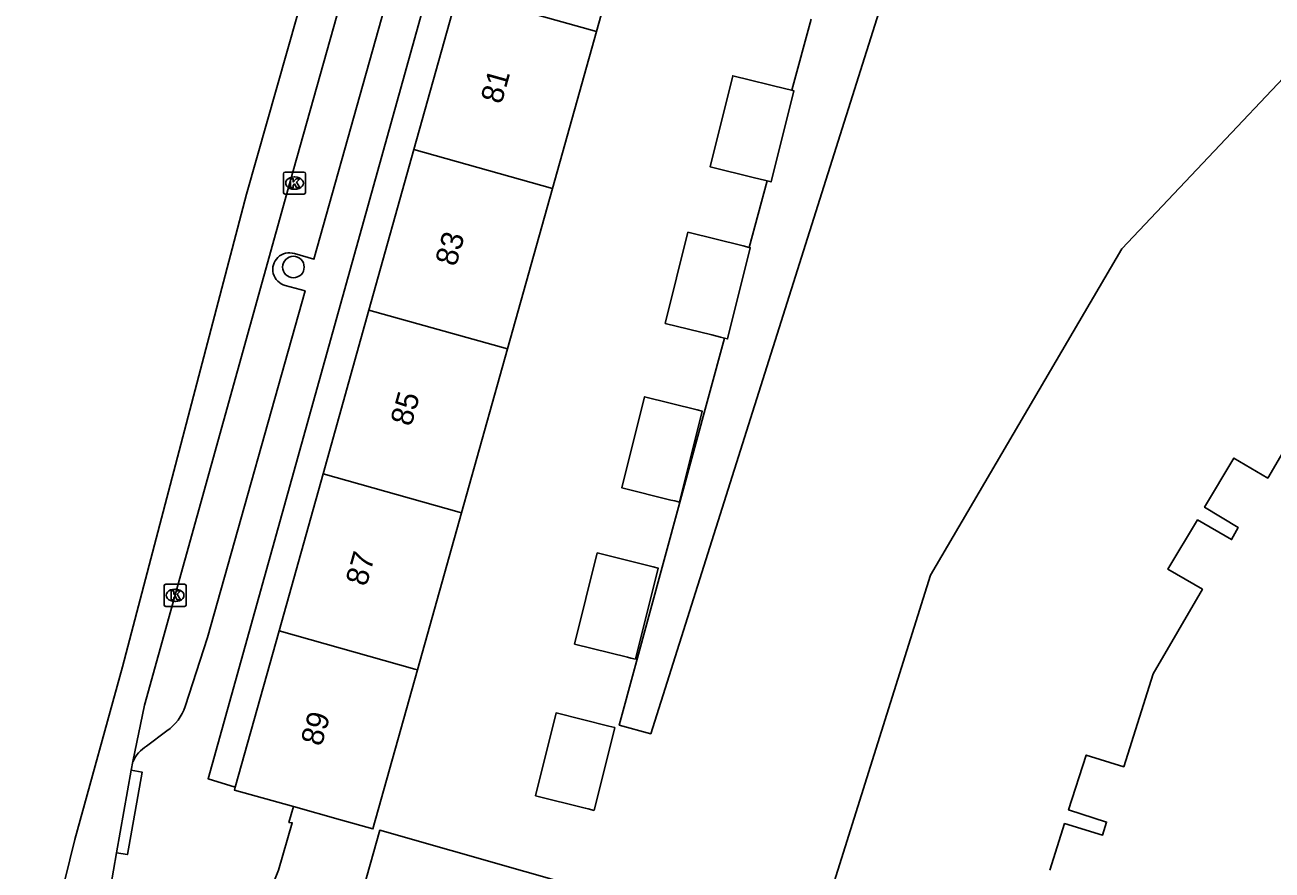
# Model space of a CAD drawing. Extents: x 163150 to 163546, y 380933 to 381635.
# Drawn here: x 163156.4 to 163213, y 381250 to 381288.4 of the extents above; entities that cross this region are included whole.
import ezdxf

# ---------------------------------------------------------------- set-up
doc = ezdxf.new("R2010")
doc.units = 0
for name, color, linetype in [('IMGEO_Boom', 7, 'Continuous'), ('IMGEO_Fietspad_gesloten', 7, 'Continuous'), ('IMGEO_Kolk', 7, 'Continuous'), ('IMGEO_Pand', 7, 'Continuous'), ('IMGEO_Pand_nummerreeks', 7, 'Continuous'), ('IMGEO_Rijbaan_lokaal_gesloten', 7, 'Continuous'), ('IMGEO_Voetpad_open', 7, 'Continuous')]:
    doc.layers.add(name, color=color, linetype=linetype)

msp = doc.modelspace()

# ---------------------------------------------------------------- linework, layer by layer
at = {"layer": 'IMGEO_Boom'}
msp.add_circle((163168.557, 381277.378), 0.489, dxfattribs=at)
at = {"layer": 'IMGEO_Fietspad_gesloten'}
for points in [[(163161.275, 381254.943), (163161.793, 381257.499), (163168.406, 381281.262), (163179.271, 381319.843), (163184.929, 381339.887), (163190.292, 381358.866), (163196.902, 381382.418), (163200.87, 381396.808), (163201.039, 381397.48), (163201.153, 381398.031), (163202.014, 381403.062), (163202.729, 381407.262)], [(163160.529, 381250.797), (163161.194, 381254.541)], [(163161.275, 381254.943), (163161.194, 381254.541)], [(163160.529, 381250.797), (163160.391, 381250), (163158.975, 381241.822), (163158.792, 381240.856)]]:
    msp.add_lwpolyline(points, dxfattribs=at)
at = {"layer": 'IMGEO_Kolk'}
for p, q in [((163168.18, 381281.688), (163169.032, 381281.688)), ((163168.105, 381280.762), (163168.105, 381281.614)), ((163168.593, 381281.468), (163168.618, 381281.468)), ((163169.106, 381281.614), (163169.106, 381280.762)), ((163169.032, 381280.688), (163168.18, 381280.688)), ((163168.616, 381280.908), (163168.591, 381280.908)), ((163162.762, 381262.978), (163163.614, 381262.978)), ((163162.687, 381262.052), (163162.687, 381262.904)), ((163163.175, 381262.758), (163163.2, 381262.758)), ((163163.688, 381262.904), (163163.688, 381262.052)), ((163163.614, 381261.978), (163162.762, 381261.978)), ((163163.198, 381262.198), (163163.173, 381262.198))]:
    msp.add_line(p, q, dxfattribs=at)
for points in [[(163168.18, 381281.688), (163169.032, 381281.688)], [(163168.105, 381280.762), (163168.105, 381281.614)], [(163168.426, 381281.388), (163168.549, 381281.388), (163168.549, 381281.237), (163168.679, 381281.388), (163168.843, 381281.388), (163168.697, 381281.237), (163168.85, 381280.988), (163168.698, 381280.988), (163168.613, 381281.152), (163168.549, 381281.085), (163168.549, 381280.988), (163168.426, 381280.988), (163168.426, 381281.388)], [(163169.106, 381281.614), (163169.106, 381280.762)], [(163169.032, 381280.688), (163168.18, 381280.688)], [(163162.762, 381262.978), (163163.614, 381262.978)], [(163162.687, 381262.052), (163162.687, 381262.904)], [(163163.008, 381262.678), (163163.131, 381262.678), (163163.131, 381262.527), (163163.261, 381262.678), (163163.425, 381262.678), (163163.279, 381262.527), (163163.432, 381262.278), (163163.28, 381262.278), (163163.195, 381262.442), (163163.131, 381262.375), (163163.131, 381262.278), (163163.008, 381262.278), (163163.008, 381262.678)], [(163163.688, 381262.904), (163163.688, 381262.052)], [(163163.614, 381261.978), (163162.762, 381261.978)]]:
    msp.add_lwpolyline(points, dxfattribs=at)
for centre, start, end in [((163168.182, 381281.612), 91.552, 178.448), ((163168.182, 381281.612), 91.552, 178.448), ((163169.03, 381281.612), 1.552, 88.448), ((163169.03, 381281.612), 1.552, 88.448), ((163168.182, 381280.764), 181.552, 268.448), ((163168.182, 381280.764), 181.552, 268.448), ((163169.03, 381280.764), 271.552, 358.448), ((163169.03, 381280.764), 271.552, 358.448), ((163162.764, 381262.902), 91.552, 178.448), ((163162.764, 381262.902), 91.552, 178.448), ((163163.612, 381262.902), 1.552, 88.448), ((163163.612, 381262.902), 1.552, 88.448), ((163162.764, 381262.054), 181.552, 268.448), ((163162.764, 381262.054), 181.552, 268.448), ((163163.612, 381262.054), 271.552, 358.448), ((163163.612, 381262.054), 271.552, 358.448)]:
    msp.add_arc(centre, 0.0765, start, end, dxfattribs=at)
for centre, major_axis, ratio, start_param, end_param in [((163168.592, 381281.188), (-0.387, 0.002), 0.722429, 4.712389, 7.853982), ((163168.617, 381281.188), (-0.39, 0.002), 0.717154, 1.570796, 4.712389), ((163163.174, 381262.478), (-0.387, 0.002), 0.722429, 4.712389, 7.853982), ((163163.199, 381262.478), (-0.39, 0.002), 0.717154, 1.570796, 4.712389)]:
    msp.add_ellipse(centre, major_axis=major_axis, ratio=ratio, start_param=start_param, end_param=end_param, dxfattribs=at)
at = {"layer": 'IMGEO_Pand'}
for points in [[(163187.968, 381233.07), (163193.271, 381250), (163197.467, 381263.396), (163206.151, 381278.206), (163217.937, 381290.687), (163232.209, 381300.168), (163248.202, 381306.183), (163251.969, 381306.664), (163251.737, 381308.49), (163248.676, 381308.083), (163248.28, 381310.782), (163251.461, 381311.208), (163254.337, 381311.635), (163256.45, 381311.907)], [(163184.36, 381295.392), (163182.308, 381288.068)], [(163176.023, 381289.839), (163174.025, 381282.711)], [(163182.308, 381288.068), (163176.023, 381289.839)], [(163182.308, 381288.068), (163180.311, 381280.941)], [(163190.057, 381281.286), (163189.94, 381281.315), (163189.487, 381281.427), (163187.471, 381281.927), (163188.499, 381286.064), (163190.967, 381285.451), (163191.174, 381285.399)], [(163190.057, 381281.286), (163190.235, 381281.242), (163191.263, 381285.377), (163191.174, 381285.399)], [(163174.025, 381282.711), (163171.985, 381275.428)], [(163174.025, 381282.711), (163180.311, 381280.941)], [(163180.311, 381280.941), (163178.271, 381273.661)], [(163188.12, 381274.155), (163187.946, 381274.198), (163187.542, 381274.298), (163185.436, 381274.821), (163186.464, 381278.957), (163188.973, 381278.334), (163189.238, 381278.268)], [(163189.238, 381278.268), (163189.294, 381278.254), (163188.266, 381274.119), (163188.12, 381274.155)], [(163171.985, 381275.428), (163169.901, 381267.992)], [(163178.271, 381273.661), (163171.985, 381275.428)], [(163178.271, 381273.661), (163176.187, 381266.224)], [(163186.078, 381266.709), (163185.862, 381266.762), (163185.692, 381266.804), (163183.469, 381267.356), (163184.497, 381271.492), (163186.889, 381270.898), (163187.106, 381270.844), (163186.078, 381266.709)], [(163214.984, 381271.543), (163212.779, 381267.801), (163211.241, 381268.709), (163209.909, 381266.474), (163211.444, 381265.551), (163211.135, 381265.008), (163209.598, 381265.9), (163208.245, 381263.661), (163209.817, 381262.755), (163207.584, 381258.916), (163206.245, 381254.695), (163204.539, 381255.229), (163203.74, 381252.742), (163205.464, 381252.19), (163205.283, 381251.598), (163203.56, 381252.116), (163202.893, 381250)], [(163169.901, 381267.992), (163167.904, 381260.863)], [(163169.901, 381267.992), (163176.077, 381266.25), (163176.187, 381266.224)], [(163176.187, 381266.224), (163174.19, 381259.096)], [(163184.083, 381259.579), (163183.865, 381259.633), (163183.726, 381259.668), (163181.316, 381260.265), (163182.344, 381264.402), (163184.892, 381263.769), (163185.111, 381263.715), (163184.083, 381259.579)], [(163165.917, 381253.773), (163167.904, 381260.863)], [(163167.904, 381260.863), (163174.071, 381259.124), (163174.19, 381259.096)], [(163174.19, 381259.096), (163172.168, 381251.88), (163170.695, 381252.293), (163168.559, 381252.891)], [(163182.206, 381252.719), (163181.934, 381252.786), (163181.803, 381252.819), (163179.546, 381253.379), (163180.481, 381257.14), (163182.868, 381256.547), (163183.14, 381256.479), (163182.206, 381252.719)], [(163168.559, 381252.891), (163165.88, 381253.641), (163165.917, 381253.773)], [(163176.505, 381240.326), (163176.676, 381240.949), (163178.615, 381246.72), (163171.597, 381248.709), (163172.477, 381251.813), (163182.305, 381249.026), (163179.49, 381240.083), (163178.632, 381237.357), (163175.923, 381238.21)]]:
    msp.add_lwpolyline(points, dxfattribs=at)
at = {"layer": 'IMGEO_Rijbaan_lokaal_gesloten'}
msp.add_lwpolyline([(163156.371, 381242.161), (163158.638, 381251.39), (163160.804, 381259.231), (163166.425, 381280.691), (163188.546, 381358.485)], dxfattribs=at)
at = {"layer": 'IMGEO_Voetpad_open'}
for points in [[(163237.977, 381426.449), (163234.394, 381426.061), (163227.903, 381401.347), (163219.779, 381373.21), (163217.039, 381362.987), (163210.152, 381338.67), (163208.061, 381330.864), (163204.278, 381316.746), (163202.976, 381313.355), (163198.372, 381299.184), (163184.779, 381256.196), (163183.349, 381256.587), (163188.12, 381274.155)], [(163165.917, 381253.773), (163164.683, 381254.152), (163178.814, 381304.825)], [(163173.36, 381294.872), (163174.233, 381294.63), (163169.487, 381277.734), (163168.599, 381277.989)], [(163191.174, 381285.399), (163192.051, 381288.626)], [(163189.238, 381278.268), (163190.057, 381281.286)], [(163168.189, 381276.546), (163169.089, 381276.301), (163164.661, 381260.561), (163163.65, 381257.434)], [(163162.816, 381256.323), (163161.892, 381255.633)], [(163161.194, 381254.541), (163161.686, 381254.454), (163161.021, 381250.71), (163160.529, 381250.797)], [(163168.559, 381252.891), (163168.354, 381252.169), (163168.503, 381252.157), (163167.882, 381250), (163167.275, 381248.476)]]:
    msp.add_lwpolyline(points, dxfattribs=at)
for centre, radius, start, end in [((163168.37, 381277.274), 0.75, 72.2349, 256.0422), ((163161.518, 381258.166), 2.254, 305.1581, 341.0526), ((163162.683, 381254.305), 1.545, 120.7697, 155.624)]:
    msp.add_arc(centre, radius, start, end, dxfattribs=at)

# ---------------------------------------------------------------- texts
at = {"layer": 'IMGEO_Pand_nummerreeks'}
for s, p in [('81', (163177.999, 381284.738)), ('83', (163175.935, 381277.37)), ('85', (163173.901, 381270.11)), ('87', (163171.867, 381262.85)), ('89', (163169.833, 381255.59))]:
    msp.add_text(s, height=1, rotation=74.3473, dxfattribs=at).set_placement(p)

doc.saveas('drawing.dxf')
